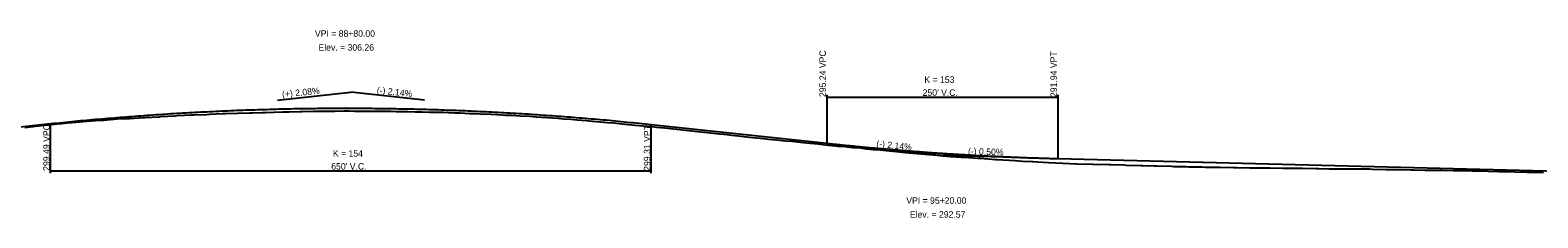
# Model space of a CAD drawing. Extents: x 1876258 to 1926563, y 729739 to 834437.
# Drawn here: x 1886896 to 1888528, y 828859 to 829061 of the extents above; entities that cross this region are included whole.
import ezdxf

# ---------------------------------------------------------------- set-up
doc = ezdxf.new("R2010")
doc.units = 0
for name, color, linetype in [('RD_EX_BldgApp', 7, 'Continuous'), ('RD_EX_H2O_BlueLn', 7, 'Continuous'), ('RD_EX_RailRoad', 7, 'Continuous'), ('RD_HC_Data', 7, 'Continuous'), ('RD_HC_TX_Sta50', 7, 'Continuous'), ('RD_PD_ALT5_CL', 7, 'Continuous')]:
    doc.layers.add(name, color=color, linetype=linetype)

msp = doc.modelspace()

# ---------------------------------------------------------------- linework, layer by layer
at = {"layer": 'RD_EX_BldgApp'}
for points in [[(1886890.3, 828956.2), (1886898.7, 828957.1), (1886908, 828958.1), (1886916.1, 828958.9), (1886925.3, 828959.9), (1886930.3, 828960.5), (1886936.3, 828961.1), (1886945.5, 828961.9), (1886952.8, 828962.5), (1886961.9, 828963.3), (1886966.5, 828963.7), (1886975.5, 828964.2), (1886990.3, 828965.4), (1886998.8, 828966), (1887002.7, 828966), (1887003.4, 828966), (1887019.1, 828967), (1887019.1, 828967), (1887020.1, 828967), (1887035.8, 828967.8), (1887036.8, 828967.9), (1887053, 828968.8), (1887055.2, 828968.9)], [(1887055.2, 828968.9), (1887062.9, 828969.3), (1887070.1, 828969.7), (1887072.7, 828969.8), (1887087.2, 828970.3), (1887090, 828970.5), (1887104.3, 828971.1), (1887107.9, 828971.2), (1887120.5, 828971.5), (1887133.2, 828971.9), (1887136.7, 828972), (1887147.4, 828972.3), (1887151.1, 828972.4), (1887169.1, 828973), (1887172.4, 828973), (1887176.1, 828973.1), (1887188.2, 828973.3), (1887190.4, 828973.3), (1887203, 828973.6), (1887205.1, 828973.6), (1887213.2, 828973.8), (1887220.2, 828973.9), (1887225.8, 828973.9), (1887235.3, 828974), (1887241, 828974), (1887247, 828973.9), (1887252.6, 828973.9), (1887259.9, 828973.8), (1887265.6, 828973.8), (1887273.1, 828973.8), (1887278.6, 828973.8), (1887286.3, 828973.6), (1887291.9, 828973.4), (1887299.2, 828973.3), (1887304.9, 828973.3), (1887312.5, 828973.2), (1887320.2, 828973), (1887328, 828972.8), (1887334.3, 828972.7), (1887342.8, 828972.5), (1887348.5, 828972.3), (1887355.7, 828972.1), (1887361.2, 828971.9), (1887371.4, 828971.4), (1887376.3, 828971.1), (1887382.9, 828970.8), (1887394.8, 828970.4), (1887401.4, 828970.1), (1887410.5, 828969.6), (1887417.1, 828969.3), (1887426.1, 828968.8), (1887436.8, 828968.2), (1887443.4, 828967.8), (1887449.5, 828967.4), (1887456.1, 828966.9), (1887467, 828966.1), (1887473.6, 828965.6), (1887481.3, 828965), (1887488, 828964.5), (1887498.2, 828963.7), (1887504.7, 828963.1), (1887512.8, 828962.4), (1887520.7, 828961.6), (1887527.3, 828961), (1887536.6, 828960.1), (1887543, 828959.5), (1887554.7, 828958.4), (1887559.7, 828957.9), (1887568.3, 828957.1), (1887573.8, 828956.6), (1887582.7, 828955.7), (1887588.9, 828955.1), (1887598.9, 828954), (1887605.1, 828953.3), (1887612, 828952.5), (1887618.3, 828951.8), (1887625.8, 828951), (1887635.5, 828950), (1887641.8, 828949.3), (1887646.7, 828948.8), (1887650.3, 828948.4), (1887655.3, 828947.9), (1887662.7, 828947.1), (1887668.2, 828946.5), (1887677.7, 828945.4), (1887682, 828944.9), (1887689.5, 828944.1), (1887695, 828943.6), (1887703.9, 828942.7), (1887713, 828941.8), (1887720.2, 828941.2), (1887726.3, 828940.6), (1887732.7, 828939.9), (1887740.2, 828939.1), (1887748.6, 828938.3), (1887756.3, 828937.5), (1887763.7, 828936.8), (1887770.3, 828936.1), (1887778, 828935.4), (1887785.9, 828934.6), (1887793.7, 828934)], [(1887793.7, 828934), (1887801, 828933.2), (1887808.2, 828932.5), (1887816.1, 828931.8), (1887825.6, 828930.8), (1887833.6, 828930), (1887842.8, 828929.1), (1887851.1, 828928.3), (1887860.2, 828927.5), (1887868.4, 828926.9), (1887877.7, 828926.1), (1887883.9, 828925.6), (1887892.1, 828924.9), (1887903.6, 828924), (1887906.9, 828924.2), (1887921.7, 828922.9), (1887923.9, 828922.8), (1887940.8, 828921.7), (1887942.2, 828921.6), (1887961.9, 828920.3), (1887962, 828920.3), (1887969.9, 828919.8), (1887980.7, 828919.3), (1887980.8, 828919.2), (1887997.9, 828918.2), (1887998.3, 828918.2), (1888013.6, 828917.5), (1888028.2, 828917), (1888028.8, 828917), (1888045.7, 828916.5), (1888046.2, 828916.5), (1888063.8, 828916), (1888065.4, 828916), (1888079.8, 828915.6), (1888082.1, 828915.5), (1888098.1, 828915.1), (1888099.8, 828915), (1888112.7, 828914.7), (1888114.8, 828914.7), (1888131.2, 828914.2), (1888133.5, 828914.1), (1888147, 828913.8), (1888149.7, 828913.7), (1888164.4, 828913.5), (1888167.7, 828913.4), (1888180.4, 828913.1), (1888183.8, 828913.1), (1888198.2, 828913), (1888201.7, 828912.9), (1888215.9, 828912.6), (1888219.4, 828912.6), (1888233.8, 828912.5), (1888237.4, 828912.5), (1888251.5, 828912.3), (1888255.1, 828912.3), (1888269.6, 828912.1), (1888273, 828912), (1888287.2, 828911.8), (1888290.7, 828911.8), (1888301.7, 828911.6), (1888303.2, 828911.6), (1888315.6, 828911.4), (1888318.8, 828911.4), (1888325.8, 828911.5), (1888329.8, 828911.4), (1888345.3, 828911.3), (1888348.7, 828911.2), (1888362.9, 828910.9), (1888367.1, 828910.8), (1888379.1, 828910.6), (1888390.1, 828910.4), (1888393.4, 828910.3), (1888405.6, 828910.1), (1888409.1, 828910), (1888420.6, 828909.9), (1888423.8, 828909.9), (1888435.9, 828909.8), (1888438.5, 828909.8), (1888441, 828909.8), (1888453.3, 828909.5), (1888456.4, 828909.4), (1888467.3, 828909.3), (1888470.9, 828909.2), (1888473.7, 828909.1), (1888485.1, 828908.7), (1888488.7, 828908.7), (1888500.2, 828908.4), (1888503.1, 828908.3), (1888515.8, 828908), (1888520.8, 828907.9), (1888533.6, 828907.5)]]:
    msp.add_lwpolyline(points, dxfattribs=at)
at = {"layer": 'RD_EX_H2O_BlueLn'}
for p, q in [((1887758.1, 828991.5), (1887758.1, 828939)), ((1887758.1, 828989), (1888008.1, 828989)), ((1888008.1, 828991.5), (1888008.1, 828922.5)), ((1886918.1, 828906.8), (1886918.1, 828960.3)), ((1887568.1, 828906.8), (1887568.1, 828959.3)), ((1886918.1, 828909.3), (1887568.1, 828909.3))]:
    msp.add_line(p, q, dxfattribs=at)
at = {"layer": 'RD_HC_TX_Sta50'}
for p, q in [((1887163.5, 828985.8), (1887243.1, 828994.1)), ((1887322.6, 828985.6), (1887243.1, 828994.1)), ((1887803.5, 828934.2), (1887883.1, 828925.7)), ((1887963.1, 828923.7), (1887883.1, 828925.7))]:
    msp.add_line(p, q, dxfattribs=at)
at = {"layer": 'RD_PD_ALT5_CL'}
for p, q in [((1886853.1, 828953.5), (1886918.1, 828960.3)), ((1887568.1, 828959.3), (1887758.1, 828939)), ((1888008.1, 828922.5), (1888573.1, 828908.4))]:
    msp.add_line(p, q, dxfattribs=at)
for points in [[(1886918.1, 828960.3), (1886931.1, 828961.6), (1886944.1, 828962.9), (1886957.1, 828964.1), (1886970.1, 828965.2), (1886983.1, 828966.3), (1886996.1, 828967.4), (1887009.1, 828968.4), (1887022.1, 828969.3), (1887035.1, 828970.2), (1887048.1, 828971.1), (1887061.1, 828971.8), (1887074.1, 828972.6), (1887087.1, 828973.2), (1887100.1, 828973.8), (1887113.1, 828974.4), (1887126.1, 828974.9), (1887139.1, 828975.3), (1887152.1, 828975.7), (1887165.1, 828976.1), (1887178.1, 828976.4), (1887191.1, 828976.6), (1887204.1, 828976.8), (1887217.1, 828976.9), (1887230.1, 828976.9), (1887243.1, 828977), (1887256.1, 828976.9), (1887269.1, 828976.8), (1887282.1, 828976.7), (1887295.1, 828976.4), (1887308.1, 828976.2), (1887321.1, 828975.9), (1887334.1, 828975.5), (1887347.1, 828975), (1887360.1, 828974.6), (1887373.1, 828974), (1887386.1, 828973.4), (1887399.1, 828972.8), (1887412.1, 828972.1), (1887425.1, 828971.3), (1887438.1, 828970.5), (1887451.1, 828969.6), (1887464.1, 828968.7), (1887477.1, 828967.7), (1887490.1, 828966.7), (1887503.1, 828965.6), (1887516.1, 828964.5), (1887529.1, 828963.3), (1887542.1, 828962), (1887555.1, 828960.7), (1887568.1, 828959.3)], [(1887758.1, 828939), (1887763.1, 828938.5), (1887768.1, 828938), (1887773.1, 828937.5), (1887778.1, 828936.9), (1887783.1, 828936.5), (1887788.1, 828936), (1887793.1, 828935.5), (1887798.1, 828935), (1887803.1, 828934.5), (1887808.1, 828934.1), (1887813.1, 828933.6), (1887818.1, 828933.2), (1887823.1, 828932.8), (1887828.1, 828932.3), (1887833.1, 828931.9), (1887838.1, 828931.5), (1887843.1, 828931.1), (1887848.1, 828930.7), (1887853.1, 828930.3), (1887858.1, 828930), (1887863.1, 828929.6), (1887868.1, 828929.2), (1887873.1, 828928.9), (1887878.1, 828928.5), (1887883.1, 828928.2), (1887888.1, 828927.9), (1887893.1, 828927.6), (1887898.1, 828927.3), (1887903.1, 828927), (1887908.1, 828926.7), (1887913.1, 828926.4), (1887918.1, 828926.1), (1887923.1, 828925.8), (1887928.1, 828925.6), (1887933.1, 828925.3), (1887938.1, 828925.1), (1887943.1, 828924.8), (1887948.1, 828924.6), (1887953.1, 828924.4), (1887958.1, 828924.2), (1887963.1, 828924), (1887968.1, 828923.8), (1887973.1, 828923.6), (1887978.1, 828923.4), (1887983.1, 828923.3), (1887988.1, 828923.1), (1887993.1, 828922.9), (1887998.1, 828922.8), (1888003.1, 828922.7), (1888008.1, 828922.5)]]:
    msp.add_spline(points, degree=3, dxfattribs=at)

# ---------------------------------------------------------------- texts
at = {"layer": 'RD_EX_H2O_BlueLn'}
for s, p in [('K = 153', (1887863.7, 829004.3)), ("250' V.C.", (1887861.8, 828990.3)), ('K = 154', (1887223.6, 828924.6)), ("650' V.C.", (1887221.8, 828910.6))]:
    msp.add_text(s, height=7, dxfattribs=at).set_placement(p)
at = {"layer": 'RD_EX_RailRoad'}
for s, p in [('295.24 VPC', (1887757.1, 828989)), ('291.94 VPT', (1888007.1, 828989)), ('299.49 VPC', (1886917.1, 828909.3)), ('299.31 VPT', (1887567.1, 828909.3))]:
    msp.add_text(s, height=7, rotation=90, dxfattribs=at).set_placement(p)
at = {"layer": 'RD_HC_Data'}
for s, p in [('VPI = 88+80.00', (1887204.1, 829054.1)), ('Elev. = 306.26', (1887208, 829039.1)), ('VPI = 95+20.00', (1887844.1, 828873.7)), ('Elev. = 292.57', (1887848, 828858.7))]:
    msp.add_text(s, height=7, dxfattribs=at).set_placement(p)
at = {"layer": 'RD_HC_TX_Sta50'}
for s, rotation, p in [('(+) 2.08%', 5.9443, (1887168.9, 828988.4)), ('(-) 2.14%', 353.8952, (1887270.8, 828993.1)), ('(-) 2.14%', 353.8952, (1887811.4, 828935.3)), ('(-) 0.50%', 358.5679, (1887910.8, 828927))]:
    msp.add_text(s, height=7, rotation=rotation, dxfattribs=at).set_placement(p)

doc.saveas('drawing.dxf')
